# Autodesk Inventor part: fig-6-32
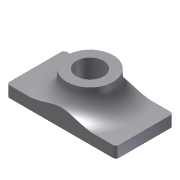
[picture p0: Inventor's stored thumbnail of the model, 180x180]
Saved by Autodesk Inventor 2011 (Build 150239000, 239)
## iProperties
Created: 2004-05
Part Number: fig-6-32
Document SubType Name: Modeling
Designer: CADCIM Technologies
Manufacturer: Standard
Standards Organization: Custom
Density: 1 g/cm^3
Author: CADCIM Technologies
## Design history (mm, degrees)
sketch "Sketch1"
  geometry: L1 (-39.276, -18.692)-(33.721, -18.692); L2 (33.721, -18.692)-(33.721, 19.728); L3 (33.721, 19.728)-(-39.276, 19.728); L4 (-39.276, 19.728)-(-39.276, -18.692)
  constraints: 8 end point, 2 parallel, 1 horizontal, 1 perpendicular
extrude "Extrusion1" new body sketch "Sketch1" distance "d0" = 7.5; taper "d1" = 0 deg
fillet "Fillet1" dims "d2" = 2
sketch "Sketch2"
  geometry: C1 r 15.456 at (-2.778, 0.518)
  constraints: 1 centre point
extrude "Extrusion2" join sketch "Sketch2" distance "d3" = 17.25; taper "d4" = 0 deg
hole "Hole1" diameter "d8" = 18; stored, may be unused: countersink angle "d12" = 90 deg, drill point angle "d14" = 118 deg; dims "d6" = 10, "d7" = 10, "d9" = 6, "d10" = 4, "d11" = 2, "d13" = 8
fillet "Fillet2" dims "d5" = 14
body "Solid1"
